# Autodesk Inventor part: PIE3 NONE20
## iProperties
Shininess: 64.0
Length Units: 11269
Angle Units: 11279
Time Units: 11290
Mass Units: 11286
Length Display Precision: 3
Angle Display Precision: 2
Compacted: True
Part Number: PIE3 NONE20
Document SubType Name: Modeling
Created: 2004-08
Designer: John Blackburn
Manufacturer: Standard
Standards Organization: Custom
Density: 0.0
Volumn: 0.0
Area: 0.0
PropertySet Name: Model Information
Control State: 0
Master: False
Checked Out: False
Author: John Blackburn
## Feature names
1. Erst1
